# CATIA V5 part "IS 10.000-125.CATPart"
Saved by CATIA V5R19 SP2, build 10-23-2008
Part number: BX 10.000-125
Bounding box of the stored display mesh (mm): x -97.324 to 97.324, y -97.5 to 97.5, z 0 to 410
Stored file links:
  C:\Users\Bora\Desktop\3D Katı model\IS serisi\IS 10.000\BX 10.000-125.CATPart
  C:\Program Files\Dassault Systemes\B19\intel_a\reffiles\standard\MetricThickPitch.txt
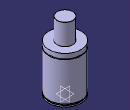
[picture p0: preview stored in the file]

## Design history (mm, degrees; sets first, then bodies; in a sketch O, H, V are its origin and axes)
Body1 (main body)
  Sketch1 on yz-plane, origin (0, 0, 0), H (0, 1, 0), V (0, 0, 1)
    point P1 (97.5, 254)
    point P4 (97.5, 249)
    point P7 (47.5, 409)
    point P9 (47.5, 409)
    point P13 (97.5, 254)
    point P14 (97.5, 249)
    line L1 (97.5, 254) -> (97.5, 282)
    line L2 (97.5, 16) -> (97.5, 249)
    line L3 (93.5, 16) -> (93.5, 8)
    arc A1 centre (46.5, 409) radius 1 from (47.5, 409) to (46.5, 410) ccw
    line L4 (47.5, 409) -> (47.5, 282)
    line L5 (97.5, 0) -> (97.5, 8)
    arc A2 centre (97.5, 251.5) radius 2.5 from (97.5, 254) to (97.5, 249) ccw
    line L6 (46.5, 410) -> (0, 410)
    point P15 (0, 410)
    line L7 (47.5, 282) -> (97.5, 282)
    line L8 (93.5, 16) -> (97.5, 16)
    line L9 (93.5, 8) -> (97.5, 8)
    line L10 (97.5, 0) -> (0, 0)
    coincidence: P15 V, P1 P13, P4 P14, P7 P9
    tangency: L6 A1
    horizontal: L7 H, L8 H, L9 H, L10 H
  Shaft1: profile Sketch1, axis Sketch1.V, angle 360
  Sketch2 on face of Shaft1 from Sketch1.L10, origin (0, 0, 0), H (1, 0, 0), V (0, -1, 0)
    point P1 (60, 0)
    distance P1 V = 60
  Hole1: placed by Sketch2, at (60, 0, 0) direction (0, 0, 1), diameter 10.106, depth 16, threaded "M12", thread diameter 12, thread depth 16, pitch 1.75
  CircPattern1: of Hole1, instances 4, angular step 90, axis from xy-plane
